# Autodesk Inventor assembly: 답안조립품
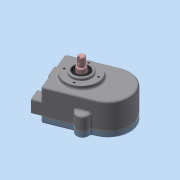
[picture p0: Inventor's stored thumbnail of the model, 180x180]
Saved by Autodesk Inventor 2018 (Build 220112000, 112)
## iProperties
Created: 2024-03
Part Number: 답안조립품
Material: 일반
Document SubType Name: Assembly
Designer: home
Author: home
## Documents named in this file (9)
- C:\Users\home\Desktop\740304V1021\답안조립품.iam
- C:\Users\home\Desktop\740304V1021\740304V1021.ipt
- C:\Users\home\Desktop\740304V1021\가스켓.ipt
- C:\Users\home\Desktop\740304V1021\구동기어.ipt
- C:\Users\home\Desktop\740304V1021\스퍼기어.ipt
- C:\Users\home\Desktop\740304V1021\오일 실 14 25 7.ipt
- C:\Users\home\Desktop\740304V1021\오일레스 부시.ipt
- C:\Users\home\Desktop\740304V1021\육각 소켓 머리 볼트 M5x12.ipt
- C:\Users\home\Desktop\740304V1021\커버.ipt
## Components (3 placed, 3 different names)
1. 740304V1021:1 — 각도:1, 각도:2, 각도:3, 각도:4
2. 가스켓:1
3. 구동기어:1
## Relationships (4: Angle 4)
- 각도:1 [Angle]: 740304V1021:1
- 각도:2 [Angle]: 740304V1021:1
- 각도:3 [Angle]: 740304V1021:1
- 각도:4 [Angle]: 740304V1021:1
